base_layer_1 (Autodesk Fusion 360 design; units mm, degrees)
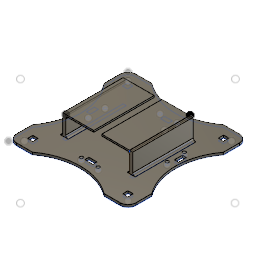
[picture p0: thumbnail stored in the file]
sketch "Sketch1" plane through (0, 0, 0) normal (0, 1, 0) x axis (1, 0, 0)
  line L1 (-15, -85) -> (-5, -85)
  line L2 (-5, -85) -> (-5, -80)
  line L3 (45.9678, -98.3934) -> (45.9678, -91.8934)
  line L4 (-15, -80) -> (-15, -85)
  line L5 (-5, -80) -> (-15, -80)
  line L6 (-50.6337, 2.6066) -> (-54.6337, 2.6066)
  line L7 (51.9678, 28.6046) -> (51.9678, 22.1046)
  line L8 (-5, 15) -> (-5, 10)
  line L9 (-15, 15) -> (-5, 15)
  line L10 (51.9678, 22.1046) -> (45.4678, 22.1046)
  line L11 (-64, -29) -> (-64, -19)
  line L12 (-76.0322, 40.1026) -> (-56.0322, 40.1026)
  line L13 (-68, 28) -> (-68, 21.5)
  line L14 (-5, 10) -> (-15, 10)
  line L15 (-74.5, 28) -> (-68, 28)
  line L16 (-74.5, 21.5) -> (-74.5, 28)
  line L17 (63.9678, 9.8155) -> (63.9678, 30.1039)
  line L18 (-86.0322, 10.1066) -> (-86.0322, 30.1026)
  line L19 (-64, -19) -> (-69, -19)
  line L20 (45.4678, 22.1046) -> (45.4678, 28.6046)
  line L21 (-68, 21.5) -> (-74.5, 21.5)
  line L22 (45.4678, 28.6046) -> (51.9678, 28.6046)
  line L23 (53.9691, 40.1039) -> (33.9678, 40.1066)
  line L24 (28.4678, 3.6066) -> (32.4678, 3.6066)
  line L25 (28.4678, -72.3934) -> (32.4678, -72.3934)
  line L26 (45.9678, -91.8934) -> (52.4678, -91.8934)
  line L27 (-69, -19) -> (-69, -29)
  line L28 (-74.03, -97.893) -> (-74.03, -91.393)
  line L29 (-54.6337, -73.3934) -> (-54.6337, 2.6066)
  line L30 (46.4751, -29) -> (46.4751, -19)
  line L31 (-15, 10) -> (-15, 15)
  line L32 (46.4751, -19) -> (41.4751, -19)
  line L33 (41.4751, -19) -> (41.4751, -29)
  line L34 (-50.6337, -73.3934) -> (-50.6337, 2.6066)
  line L35 (32.4678, -72.3934) -> (32.4678, 3.6066)
  line L36 (41.4751, -29) -> (46.4751, -29)
  line L37 (-50.6337, -73.3934) -> (-54.6337, -73.3934)
  line L38 (-67.53, -97.893) -> (-74.03, -97.893)
  line L39 (63.9678, -79.8934) -> (63.9678, -99.8934)
  line L40 (-86.0322, -99.8934) -> (-86.0322, -79.8934)
  line L41 (28.4678, 3.6066) -> (28.4678, -72.3934)
  line L42 (-67.53, -91.393) -> (-67.53, -97.893)
  line L43 (53.9678, -109.8934) -> (33.9678, -109.8934)
  line L44 (-74.03, -91.393) -> (-67.53, -91.393)
  line L45 (52.4678, -98.3934) -> (45.9678, -98.3934)
  line L46 (52.4678, -91.8934) -> (52.4678, -98.3934)
  line L47 (-69, -29) -> (-64, -29)
  line L48 (-76.0322, -109.8934) -> (-56.0322, -109.8934)
  arc A1 centre (-76.0322, 30.1026) radius 10 clockwise from (-86.0322, 30.1026) to (-76.0322, 40.1026)
  arc A2 centre (53.9678, 30.1039) radius 10 clockwise from (53.9691, 40.1039) to (63.9678, 30.1039)
  arc A3 centre (-11.0349, 100.0947) radius 74.9921 clockwise from (33.9678, 40.1066) to (-56.0322, 40.1026)
  arc A4 centre (123.5319, -35.039) radius 74.5641 clockwise from (63.9678, -79.8934) to (63.9678, 9.8155)
  arc A5 centre (-146.0322, -34.8934) radius 75 clockwise from (-86.0322, 10.1066) to (-86.0322, -79.8934)
  arc A6 centre (-76.0322, -99.8934) radius 10 clockwise from (-76.0322, -109.8934) to (-86.0322, -99.8934)
  arc A7 centre (-11.0322, -169.8934) radius 75 clockwise from (-56.0322, -109.8934) to (33.9678, -109.8934)
  arc A8 centre (53.9678, -99.8934) radius 10 clockwise from (63.9678, -99.8934) to (53.9678, -109.8934)
  circle C1 centre (-61.0322, -13.6974) radius 2
  circle C2 centre (-61.0322, -34.6974) radius 2
  circle C3 centre (-20.5269, 14.8155) radius 2
  circle C4 centre (0.4731, 15.3155) radius 2
  circle C5 centre (39.4678, -14.6974) radius 2
  circle C6 centre (38.9678, -35.6974) radius 2
  circle C7 centre (-19.5269, -84.8934) radius 2
  circle C8 centre (1.4731, -84.8934) radius 2
  point P22 (-50.6337, -73.3934)
  point P25 (-54.6337, -73.3934)
  point P20 (32.4678, -72.3934)
  point P24 (28.4678, -72.3934)
  point P19 (-54.6337, 2.6066)
  point P21 (-50.6337, 2.6066)
  point P18 (28.4678, 3.6066)
  point P23 (32.4678, 3.6066)
  point P34 (-5, -80)
  point P37 (-15, -80)
  point P43 (-15, -85)
  point P35 (-5, 10)
  point P38 (-15, 10)
  point P47 (-69, -29)
  point P48 (-69, -19)
  point P36 (41.4751, -19)
  point P46 (46.4751, -19)
  point P42 (41.4751, -29)
  point P57 (-74.03, -97.893)
  point P66 (-74.03, -91.393)
  point P62 (-67.53, -97.893)
  dimension "d5" distance P22 P25 = 4
  dimension "d6" distance P20 P24 = 4
  dimension "d7" distance P19 P21 = 4
  dimension "d8" distance P18 P23 = 4
  dimension "d13" distance P34 P37 = 10
  dimension "d14" distance P37 P43 = 5
  dimension "d15" distance P35 P38 = 10
  dimension "d17" distance P47 P48 = 10
  dimension "d18" distance P36 P46 = 5
  dimension "d19" distance P36 P42 = 10
  dimension "d20" radius A1 = 10
  dimension "d21" distance P57 P66 = 6.5
  dimension "d22" distance P57 P62 = 6.5
  dimension "d61" distance L15 L21 = 6.5
  dimension "d62" distance L13 L16 = 6.5
  dimension "d63" distance L10 L22 = 6.5
  dimension "d64" distance L7 L20 = 6.5
  dimension "d65" distance L3 L46 = 6.5
  dimension "d66" distance L26 L45 = 6.5
  dimension "d67" distance P19 P25 = 76
  dimension "d68" distance P20 P23 = 76
  dimension "d69" diameter C1 = 4
  dimension "d70" diameter C2 = 4
  dimension "d71" diameter C3 = 4
  dimension "d72" diameter C4 = 4
  dimension "d73" diameter C5 = 4
  dimension "d74" diameter C6 = 4
  dimension "d75" diameter C7 = 4
  dimension "d76" diameter C8 = 4
extrude "Extrude2" new body sketch "Sketch1" profile of L6 L24 L25 L29 L34 L35 L37 L41 along normal blind 28.5
extrude "Extrude1" new body sketch "Sketch1" along normal blind 3
sketch "Sketch2" plane through (-50.6337, 0, 0) normal (1, 0, 0) x axis (0, 0, -1)
  line L1 (2.6066, 0) -> (-73.3934, 0)
  line L2 (2.6066, 28.5) -> (2.6066, 0)
  line L3 (-73.3934, 28.5) -> (2.6066, 28.5)
  line L4 (-73.3934, 0) -> (-73.3934, 28.5)
  line L5 (2.6066, 28.5) -> (-73.3934, 28.5)
  line L6 (2.6066, 26.5) -> (2.6066, 28.5)
  line L7 (-73.3934, 26.5) -> (2.6066, 26.5)
  line L8 (-73.3934, 28.5) -> (-73.3934, 26.5)
  point P6 (-73.3934, 28.5)
  point P9 (-73.3934, 26.5)
  dimension "d81" distance P6 P9 = 2
extrude "Extrude3" add sketch "Sketch2" profile of L2 L3 L4 L5 L6 L7 L8 along normal blind 35
sketch "Sketch3" plane through (28.4678, 0, 0) normal (-1, 0, 0) x axis (0, 0, 1)
  line L1 (72.3934, 0) -> (-3.6066, 0)
  line L2 (72.3934, 28.5) -> (72.3934, 0)
  line L3 (-3.6066, 28.5) -> (72.3934, 28.5)
  line L4 (-3.6066, 0) -> (-3.6066, 28.5)
  line L5 (72.3934, 28.5) -> (-3.6066, 28.5)
  line L6 (72.3934, 26.5) -> (72.3934, 28.5)
  line L7 (-3.6066, 26.5) -> (72.3934, 26.5)
  line L8 (-3.6066, 28.5) -> (-3.6066, 26.5)
  point P6 (-3.6066, 28.5)
  point P9 (-3.6066, 26.5)
  dimension "d84" distance P6 P9 = 2
extrude "Extrude4" add sketch "Sketch3" profile of L2 L3 L4 L5 L6 L7 L8 along normal blind 35
fillet "Fillet1" radius 3
fillet "Fillet2" radius 3
combine "Combine1"
fillet "Fillet3" radius 3
fillet "Fillet4" radius 3
combine "Combine2"
fillet "Fillet5" radius 3
fillet "Fillet6" radius 3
